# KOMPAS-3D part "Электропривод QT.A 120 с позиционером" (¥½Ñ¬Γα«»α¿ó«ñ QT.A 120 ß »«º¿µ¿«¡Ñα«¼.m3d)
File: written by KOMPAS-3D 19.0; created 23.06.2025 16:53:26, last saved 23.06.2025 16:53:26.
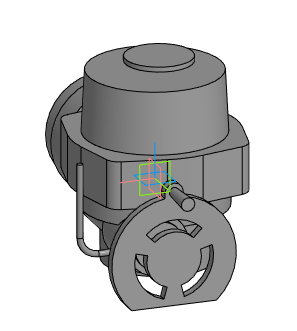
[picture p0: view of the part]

Document properties: Автор: Евгений; Полное имя файла: E:\Dendor Работа Сачек\3D для проектировщиков\3.5 Тип QT.А Электропривод\stp_Электропривод QT.A с позиционером\Электропривод QT.A 120 с позиционером.m3d

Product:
- Part/product: Электропривод QT.A 120 с позиционером

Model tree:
1. Операция без истории:1  (labels: Электропривод QT.A 120 с позиционером)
